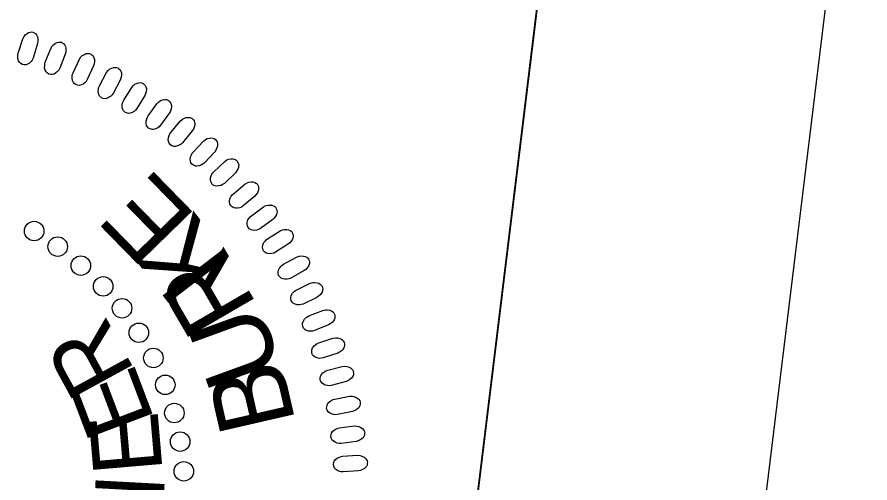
# Model space of a CAD drawing. Extents: x 480570 to 481861, y 488765 to 490569.
# Drawn here: x 480900.2 to 480970.2, y 490487.4 to 490525.7 of the extents above; entities that cross this region are included whole.
import ezdxf

# ---------------------------------------------------------------- set-up
doc = ezdxf.new("R2010")
doc.units = 0
for name, color, linetype in [('Sheet PE Seal Cell', 7, 'Continuous'), ('Sheet Plan CELL', 7, 'Continuous'), ('Sheet Sticker Exception Certification CELL', 7, 'Continuous')]:
    doc.layers.add(name, color=color, linetype=linetype)

msp = doc.modelspace()

# ---------------------------------------------------------------- linework, layer by layer
at = {"layer": 'Sheet PE Seal Cell'}
for points in [[(480900.253, 490522.716), (480900.628, 490523.884), (480900.731, 490524.081), (480900.823, 490524.199), (480900.982, 490524.326), (480901.108, 490524.4), (480901.239, 490524.442), (480901.351, 490524.448), (480901.464, 490524.433), (480901.564, 490524.38), (480901.669, 490524.315), (480901.75, 490524.226), (480901.819, 490524.098), (480901.852, 490524.004), (480901.871, 490523.842), (480901.873, 490523.652), (480901.846, 490523.494), (480901.469, 490522.295), (480901.395, 490522.14), (480901.31, 490522.021), (480901.176, 490521.897), (480901.027, 490521.798), (480900.91, 490521.751), (480900.742, 490521.742), (480900.593, 490521.769), (480900.463, 490521.853), (480900.379, 490521.932), (480900.288, 490522.066), (480900.226, 490522.264), (480900.217, 490522.456), (480900.229, 490522.588)], [(480902.477, 490521.959), (480902.925, 490523.102), (480903.04, 490523.292), (480903.139, 490523.403), (480903.305, 490523.521), (480903.436, 490523.587), (480903.57, 490523.62), (480903.681, 490523.619), (480903.793, 490523.597), (480903.89, 490523.538), (480903.991, 490523.466), (480904.066, 490523.372), (480904.127, 490523.241), (480904.154, 490523.145), (480904.162, 490522.981), (480904.152, 490522.792), (480904.115, 490522.636), (480903.664, 490521.463), (480903.581, 490521.313), (480903.488, 490521.199), (480903.347, 490521.083), (480903.191, 490520.995), (480903.072, 490520.956), (480902.904, 490520.957), (480902.757, 490520.993), (480902.632, 490521.085), (480902.553, 490521.169), (480902.471, 490521.309), (480902.422, 490521.51), (480902.424, 490521.702), (480902.444, 490521.833)], [(480904.757, 490521.104), (480905.275, 490522.216), (480905.402, 490522.399), (480905.508, 490522.504), (480905.682, 490522.61), (480905.816, 490522.668), (480905.952, 490522.693), (480906.063, 490522.685), (480906.173, 490522.656), (480906.266, 490522.591), (480906.362, 490522.512), (480906.432, 490522.415), (480906.484, 490522.28), (480906.505, 490522.182), (480906.502, 490522.018), (480906.481, 490521.83), (480906.434, 490521.676), (480905.91, 490520.534), (480905.818, 490520.39), (480905.718, 490520.282), (480905.57, 490520.175), (480905.409, 490520.096), (480905.287, 490520.065), (480905.12, 490520.077), (480904.975, 490520.123), (480904.857, 490520.222), (480904.783, 490520.311), (480904.71, 490520.455), (480904.674, 490520.659), (480904.688, 490520.851), (480904.716, 490520.98)], [(480906.921, 490520.032), (480907.508, 490521.11), (480907.646, 490521.284), (480907.758, 490521.382), (480907.939, 490521.477), (480908.076, 490521.527), (480908.213, 490521.543), (480908.323, 490521.528), (480908.432, 490521.492), (480908.521, 490521.421), (480908.611, 490521.338), (480908.675, 490521.235), (480908.719, 490521.097), (480908.733, 490520.998), (480908.72, 490520.835), (480908.687, 490520.649), (480908.63, 490520.498), (480908.036, 490519.391), (480907.935, 490519.253), (480907.829, 490519.152), (480907.673, 490519.055), (480907.509, 490518.985), (480907.385, 490518.962), (480907.218, 490518.984), (480907.078, 490519.038), (480906.965, 490519.145), (480906.897, 490519.239), (480906.833, 490519.387), (480906.81, 490519.593), (480906.837, 490519.784), (480906.872, 490519.911)], [(480908.911, 490518.86), (480909.564, 490519.898), (480909.714, 490520.064), (480909.831, 490520.155), (480910.017, 490520.238), (480910.158, 490520.28), (480910.295, 490520.287), (480910.405, 490520.265), (480910.51, 490520.222), (480910.594, 490520.146), (480910.68, 490520.056), (480910.737, 490519.95), (480910.772, 490519.81), (480910.78, 490519.711), (480910.757, 490519.548), (480910.712, 490519.365), (480910.646, 490519.218), (480909.983, 490518.15), (480909.874, 490518.018), (480909.761, 490517.924), (480909.601, 490517.837), (480909.432, 490517.779), (480909.307, 490517.763), (480909.142, 490517.796), (480909.005, 490517.859), (480908.9, 490517.972), (480908.838, 490518.07), (480908.783, 490518.222), (480908.772, 490518.429), (480908.811, 490518.617), (480908.855, 490518.742)], [(480910.916, 490517.559), (480911.633, 490518.554), (480911.792, 490518.71), (480911.916, 490518.793), (480912.106, 490518.865), (480912.249, 490518.897), (480912.387, 490518.896), (480912.495, 490518.867), (480912.597, 490518.818), (480912.677, 490518.736), (480912.756, 490518.642), (480912.806, 490518.533), (480912.833, 490518.39), (480912.835, 490518.29), (480912.802, 490518.129), (480912.745, 490517.949), (480912.67, 490517.807), (480911.942, 490516.782), (480911.824, 490516.658), (480911.706, 490516.571), (480911.54, 490516.495), (480911.367, 490516.446), (480911.242, 490516.439), (480911.08, 490516.482), (480910.946, 490516.553), (480910.849, 490516.673), (480910.793, 490516.775), (480910.748, 490516.93), (480910.75, 490517.137), (480910.801, 490517.323), (480910.852, 490517.445)], [(480912.775, 490516.186), (480913.553, 490517.135), (480913.722, 490517.28), (480913.85, 490517.355), (480914.045, 490517.415), (480914.189, 490517.438), (480914.327, 490517.429), (480914.433, 490517.393), (480914.532, 490517.337), (480914.606, 490517.251), (480914.68, 490517.152), (480914.723, 490517.039), (480914.74, 490516.896), (480914.736, 490516.796), (480914.693, 490516.637), (480914.625, 490516.461), (480914.542, 490516.323), (480913.749, 490515.347), (480913.624, 490515.231), (480913.501, 490515.151), (480913.331, 490515.085), (480913.156, 490515.048), (480913.03, 490515.048), (480912.871, 490515.101), (480912.742, 490515.181), (480912.652, 490515.306), (480912.603, 490515.412), (480912.568, 490515.569), (480912.583, 490515.776), (480912.645, 490515.958), (480912.704, 490516.077)], [(480914.611, 490514.591), (480915.447, 490515.488), (480915.624, 490515.623), (480915.757, 490515.69), (480915.955, 490515.738), (480916.101, 490515.752), (480916.238, 490515.734), (480916.341, 490515.692), (480916.437, 490515.63), (480916.505, 490515.539), (480916.573, 490515.435), (480916.608, 490515.32), (480916.616, 490515.176), (480916.606, 490515.076), (480916.553, 490514.921), (480916.474, 490514.749), (480916.382, 490514.617), (480915.531, 490513.693), (480915.399, 490513.584), (480915.271, 490513.513), (480915.097, 490513.457), (480914.919, 490513.431), (480914.794, 490513.439), (480914.638, 490513.502), (480914.515, 490513.59), (480914.433, 490513.72), (480914.39, 490513.828), (480914.365, 490513.988), (480914.393, 490514.194), (480914.467, 490514.371), (480914.533, 490514.486)], [(480916.307, 490512.969), (480917.198, 490513.812), (480917.383, 490513.935), (480917.52, 490513.994), (480917.721, 490514.029), (480917.867, 490514.033), (480918.002, 490514.007), (480918.103, 490513.958), (480918.195, 490513.89), (480918.256, 490513.795), (480918.317, 490513.687), (480918.346, 490513.571), (480918.345, 490513.426), (480918.328, 490513.328), (480918.266, 490513.176), (480918.177, 490513.009), (480918.076, 490512.883), (480917.169, 490512.014), (480917.03, 490511.914), (480916.897, 490511.851), (480916.721, 490511.806), (480916.542, 490511.791), (480916.417, 490511.808), (480916.265, 490511.88), (480916.149, 490511.976), (480916.075, 490512.111), (480916.039, 490512.222), (480916.024, 490512.382), (480916.065, 490512.585), (480916.149, 490512.758), (480916.223, 490512.869)], [(480917.911, 490511.166), (480918.853, 490511.952), (480919.046, 490512.064), (480919.187, 490512.113), (480919.389, 490512.135), (480919.535, 490512.131), (480919.668, 490512.096), (480919.766, 490512.041), (480919.853, 490511.967), (480919.91, 490511.869), (480919.963, 490511.757), (480919.985, 490511.64), (480919.974, 490511.495), (480919.952, 490511.398), (480919.88, 490511.25), (480919.78, 490511.089), (480919.672, 490510.97), (480918.712, 490510.16), (480918.567, 490510.068), (480918.43, 490510.014), (480918.251, 490509.98), (480918.072, 490509.977), (480917.948, 490510.001), (480917.802, 490510.082), (480917.691, 490510.185), (480917.626, 490510.325), (480917.597, 490510.438), (480917.592, 490510.599), (480917.646, 490510.799), (480917.741, 490510.966), (480917.821, 490511.072)], [(480919.397, 490509.361), (480920.387, 490510.086), (480920.586, 490510.185), (480920.73, 490510.226), (480920.933, 490510.235), (480921.079, 490510.222), (480921.209, 490510.178), (480921.303, 490510.117), (480921.386, 490510.038), (480921.435, 490509.936), (480921.482, 490509.822), (480921.496, 490509.703), (480921.477, 490509.559), (480921.448, 490509.463), (480921.367, 490509.321), (480921.257, 490509.166), (480921.142, 490509.054), (480920.133, 490508.306), (480919.983, 490508.224), (480919.843, 490508.178), (480919.662, 490508.155), (480919.483, 490508.163), (480919.361, 490508.195), (480919.22, 490508.286), (480919.116, 490508.395), (480919.06, 490508.539), (480919.038, 490508.653), (480919.043, 490508.815), (480919.109, 490509.011), (480919.214, 490509.172), (480919.301, 490509.272)], [(480920.705, 490507.455), (480921.738, 490508.117), (480921.943, 490508.204), (480922.089, 490508.235), (480922.292, 490508.232), (480922.437, 490508.209), (480922.565, 490508.157), (480922.655, 490508.091), (480922.732, 490508.007), (480922.775, 490507.902), (480922.814, 490507.785), (480922.821, 490507.665), (480922.793, 490507.523), (480922.759, 490507.429), (480922.669, 490507.292), (480922.549, 490507.145), (480922.427, 490507.04), (480921.373, 490506.357), (480921.218, 490506.284), (480921.076, 490506.247), (480920.893, 490506.236), (480920.716, 490506.255), (480920.596, 490506.295), (480920.461, 490506.394), (480920.363, 490506.509), (480920.317, 490506.657), (480920.302, 490506.772), (480920.317, 490506.933), (480920.396, 490507.125), (480920.511, 490507.279), (480920.604, 490507.374)], [(480922.028, 490505.373), (480923.101, 490505.968), (480923.31, 490506.042), (480923.458, 490506.065), (480923.66, 490506.049), (480923.804, 490506.016), (480923.928, 490505.957), (480924.013, 490505.885), (480924.085, 490505.796), (480924.122, 490505.689), (480924.154, 490505.57), (480924.153, 490505.449), (480924.116, 490505.309), (480924.075, 490505.218), (480923.977, 490505.087), (480923.849, 490504.947), (480923.721, 490504.85), (480922.626, 490504.234), (480922.466, 490504.172), (480922.322, 490504.144), (480922.139, 490504.144), (480921.963, 490504.174), (480921.846, 490504.221), (480921.717, 490504.329), (480921.627, 490504.451), (480921.59, 490504.601), (480921.583, 490504.716), (480921.608, 490504.876), (480921.698, 490505.062), (480921.823, 490505.209), (480921.921, 490505.297)], [(480923.11, 490503.283), (480924.219, 490503.809), (480924.433, 490503.869), (480924.581, 490503.882), (480924.783, 490503.854), (480924.924, 490503.813), (480925.044, 490503.746), (480925.125, 490503.669), (480925.191, 490503.576), (480925.221, 490503.466), (480925.245, 490503.345), (480925.236, 490503.225), (480925.191, 490503.088), (480925.145, 490502.999), (480925.038, 490502.874), (480924.902, 490502.743), (480924.768, 490502.655), (480923.636, 490502.109), (480923.473, 490502.056), (480923.328, 490502.037), (480923.145, 490502.049), (480922.97, 490502.091), (480922.857, 490502.145), (480922.735, 490502.26), (480922.653, 490502.387), (480922.625, 490502.539), (480922.625, 490502.655), (480922.66, 490502.813), (480922.762, 490502.993), (480922.896, 490503.131), (480923, 490503.213)], [(480924.112, 490501.126), (480925.251, 490501.582), (480925.469, 490501.629), (480925.618, 490501.632), (480925.817, 490501.592), (480925.955, 490501.542), (480926.071, 490501.467), (480926.147, 490501.385), (480926.207, 490501.288), (480926.23, 490501.177), (480926.246, 490501.055), (480926.23, 490500.936), (480926.176, 490500.802), (480926.124, 490500.716), (480926.01, 490500.598), (480925.866, 490500.476), (480925.726, 490500.396), (480924.562, 490499.922), (480924.397, 490499.88), (480924.25, 490499.87), (480924.069, 490499.893), (480923.898, 490499.945), (480923.787, 490500.006), (480923.673, 490500.13), (480923.599, 490500.261), (480923.581, 490500.414), (480923.588, 490500.531), (480923.633, 490500.685), (480923.747, 490500.859), (480923.889, 490500.989), (480923.998, 490501.064)], [(480924.913, 490498.911), (480926.079, 490499.294), (480926.298, 490499.327), (480926.447, 490499.322), (480926.644, 490499.268), (480926.778, 490499.21), (480926.889, 490499.128), (480926.96, 490499.042), (480927.014, 490498.941), (480927.029, 490498.829), (480927.038, 490498.705), (480927.015, 490498.587), (480926.952, 490498.457), (480926.896, 490498.375), (480926.775, 490498.264), (480926.622, 490498.152), (480926.478, 490498.08), (480925.287, 490497.681), (480925.119, 490497.649), (480924.972, 490497.648), (480924.792, 490497.683), (480924.625, 490497.746), (480924.519, 490497.814), (480924.412, 490497.944), (480924.347, 490498.08), (480924.338, 490498.234), (480924.353, 490498.349), (480924.407, 490498.501), (480924.531, 490498.667), (480924.681, 490498.788), (480924.795, 490498.856)], [(480925.655, 490496.677), (480926.842, 490496.986), (480927.063, 490497.005), (480927.212, 490496.99), (480927.404, 490496.924), (480927.535, 490496.858), (480927.64, 490496.769), (480927.705, 490496.679), (480927.753, 490496.575), (480927.761, 490496.461), (480927.763, 490496.338), (480927.732, 490496.222), (480927.661, 490496.095), (480927.599, 490496.017), (480927.471, 490495.914), (480927.313, 490495.812), (480927.164, 490495.749), (480925.95, 490495.425), (480925.78, 490495.404), (480925.634, 490495.413), (480925.457, 490495.459), (480925.294, 490495.532), (480925.192, 490495.606), (480925.094, 490495.742), (480925.037, 490495.883), (480925.038, 490496.037), (480925.061, 490496.151), (480925.125, 490496.299), (480925.258, 490496.457), (480925.415, 490496.569), (480925.533, 490496.629)], [(480926.229, 490494.297), (480927.433, 490494.531), (480927.655, 490494.537), (480927.803, 490494.513), (480927.991, 490494.435), (480928.117, 490494.36), (480928.217, 490494.265), (480928.276, 490494.17), (480928.316, 490494.063), (480928.318, 490493.95), (480928.312, 490493.827), (480928.273, 490493.713), (480928.195, 490493.591), (480928.128, 490493.517), (480927.994, 490493.423), (480927.83, 490493.329), (480927.677, 490493.277), (480926.446, 490493.029), (480926.275, 490493.019), (480926.129, 490493.037), (480925.956, 490493.094), (480925.797, 490493.177), (480925.7, 490493.258), (480925.611, 490493.401), (480925.563, 490493.543), (480925.574, 490493.697), (480925.603, 490493.81), (480925.676, 490493.954), (480925.82, 490494.103), (480925.984, 490494.204), (480926.104, 490494.258)], [(480926.617, 490491.941), (480927.834, 490492.099), (480928.056, 490492.09), (480928.202, 490492.057), (480928.385, 490491.967), (480928.506, 490491.885), (480928.6, 490491.784), (480928.653, 490491.686), (480928.686, 490491.577), (480928.681, 490491.464), (480928.667, 490491.341), (480928.622, 490491.229), (480928.536, 490491.112), (480928.465, 490491.043), (480928.325, 490490.957), (480928.154, 490490.875), (480927.999, 490490.832), (480926.754, 490490.662), (480926.583, 490490.662), (480926.439, 490490.689), (480926.269, 490490.757), (480926.116, 490490.85), (480926.024, 490490.937), (480925.945, 490491.084), (480925.906, 490491.231), (480925.926, 490491.383), (480925.962, 490491.494), (480926.044, 490491.633), (480926.197, 490491.773), (480926.367, 490491.864), (480926.491, 490491.91)], [(480926.874, 490489.607), (480928.099, 490489.688), (480928.32, 490489.666), (480928.463, 490489.623), (480928.639, 490489.522), (480928.755, 490489.432), (480928.843, 490489.326), (480928.889, 490489.224), (480928.916, 490489.113), (480928.903, 490489), (480928.882, 490488.879), (480928.829, 490488.77), (480928.737, 490488.66), (480928.661, 490488.595), (480928.516, 490488.518), (480928.341, 490488.446), (480928.183, 490488.413), (480926.93, 490488.322), (480926.76, 490488.333), (480926.617, 490488.369), (480926.452, 490488.447), (480926.305, 490488.549), (480926.219, 490488.641), (480926.149, 490488.794), (480926.119, 490488.942), (480926.15, 490489.093), (480926.192, 490489.201), (480926.283, 490489.335), (480926.444, 490489.465), (480926.619, 490489.545), (480926.746, 490489.583)]]:
    msp.add_lwpolyline(points, close=True, dxfattribs=at)
for centre in [(480901.564, 490508.099), (480903.494, 490506.82), (480905.39, 490505.264), (480907.228, 490503.554), (480908.774, 490501.76), (480910.156, 490499.749), (480911.347, 490497.678), (480912.321, 490495.473), (480913.068, 490493.158), (480913.544, 490490.813), (480913.846, 490488.37)]:
    msp.add_circle(centre, 0.801, dxfattribs=at)
at = {"layer": 'Sheet Plan CELL'}
for points in [[(480819.562, 490445.095), (480831.672, 490544.346), (480943.356, 490530.718), (480931.245, 490431.454)], [(481654.799, 488932.664), (480612.566, 489059.935), (480770.135, 490350.338), (480919.092, 490332.157), (480943.356, 490530.718), (481836.655, 490421.612)]]:
    msp.add_lwpolyline(points, close=True, dxfattribs=at)
at = {"layer": 'Sheet Sticker Exception Certification CELL'}
for p, q in [((480919.092, 490332.157), (480943.344, 490530.719)), ((480919.092, 490332.157), (480943.344, 490530.719)), ((480966.67, 490527.87), (480942.419, 490329.308)), ((480966.67, 490527.87), (480942.419, 490329.308))]:
    msp.add_line(p, q, dxfattribs=at)

# ---------------------------------------------------------------- texts
at = {"layer": 'Sheet PE Seal Cell'}
for s, height, rotation, p in [('E', 6.236, 134.30119, (480915.006, 490509.238)), ('K', 6.236, 127.45554, (480917.942, 490505.449)), ('R', 6.236, 120.18051, (480919.925, 490501.951)), ('U', 6.236, 110.08066, (480921.978, 490496.76)), ('R', 5.669, 118.69649, (480909.901, 490496.534)), ('E', 5.669, 110.7567, (480911.49, 490492.531)), ('B', 6.236, 102.96382, (480923.036, 490492.38)), ('E', 5.669, 94.8771, (480912.11, 490488.355)), ('N', 5.669, 86.93731, (480912.003, 490482.476))]:
    msp.add_text(s, height=height, rotation=rotation, dxfattribs=at).set_placement(p)

doc.saveas('drawing.dxf')
